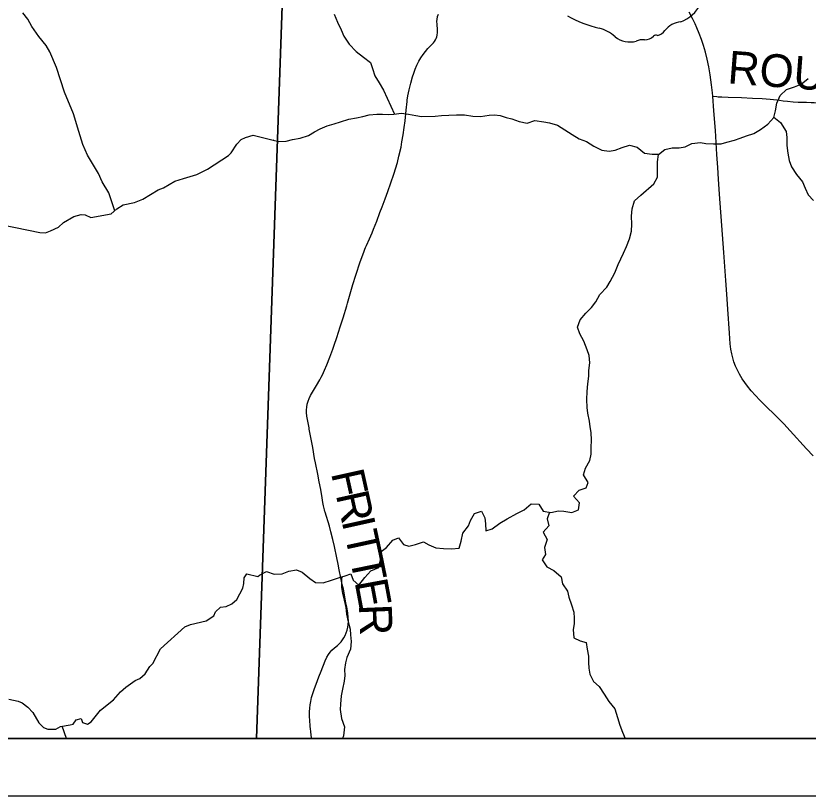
# Model space of a CAD drawing. Extents: x 0 to 34, y 0 to 22.
# Drawn here: x 28.101 to 29.474, y 14 to 15.353 of the extents above; entities that cross this region are included whole.
import ezdxf

# ---------------------------------------------------------------- set-up
doc = ezdxf.new("R2010")
doc.units = 0
for name, color, linetype in [('GM_X_Adjacent_County', 7, 'Continuous'), ('GM_X_County', 7, 'Continuous'), ('GM_X_County_Road', 7, 'Continuous'), ('GM_X_County_Road_Text', 7, 'Continuous'), ('GM_X_Minor_River', 7, 'Continuous'), ('GM_X_State_Route', 7, 'Continuous'), ('GM_X_State_Shield', 7, 'Continuous'), ('GM_X_Township', 7, 'Continuous'), ('SH_Data', 7, 'Continuous')]:
    doc.layers.add(name, color=color, linetype=linetype)

msp = doc.modelspace()

# ---------------------------------------------------------------- linework, layer by layer
at = {"layer": 'GM_X_Adjacent_County'}
for points in [[(28.7526, 20.9), (24.0167, 20.9), (24.0167, 14.1), (28.5181, 14.1)], [(28.5181, 14.1), (30.8167, 14.1), (30.8167, 20.9), (28.7526, 20.9)], [(28.5873, 16.0794), (28.5181, 14.1)], [(28.5181, 14.1), (28.5873, 16.0794)]]:
    msp.add_lwpolyline(points, dxfattribs=at)
at = {"layer": 'GM_X_County'}
for points in [[(28.7526, 20.9), (24.0167, 20.9), (24.0167, 14.1), (28.5181, 14.1)], [(28.5181, 14.1), (30.8167, 14.1), (30.8167, 20.9), (28.7526, 20.9)], [(28.5181, 14.1), (28.5873, 16.0794)], [(28.5873, 16.0794), (28.5181, 14.1)]]:
    msp.add_lwpolyline(points, dxfattribs=at)
at = {"layer": 'GM_X_County_Road'}
for points in [[(28.6133, 14.1), (28.6125, 14.1072), (28.6122, 14.1102), (28.6118, 14.1133), (28.6115, 14.1158), (28.6109, 14.122), (28.61, 14.1312), (28.6097, 14.138), (28.6097, 14.146), (28.61, 14.1528), (28.6106, 14.1582), (28.6117, 14.1643), (28.6134, 14.1709), (28.616, 14.1797), (28.6185, 14.1867), (28.6214, 14.1942), (28.6261, 14.207), (28.63, 14.2169), (28.637, 14.2347), (28.6398, 14.2408), (28.6425, 14.2456), (28.6453, 14.2496), (28.6485, 14.2532), (28.6532, 14.2572), (28.6581, 14.261), (28.6618, 14.2644), (28.6647, 14.2677), (28.667, 14.2707), (28.6693, 14.2744), (28.6713, 14.2783), (28.6732, 14.283), (28.6748, 14.2877), (28.676, 14.2932), (28.6767, 14.2976), (28.677, 14.3032), (28.6767, 14.3095), (28.6758, 14.3175), (28.6742, 14.328), (28.6729, 14.3353), (28.6683, 14.3585), (28.6665, 14.367), (28.6638, 14.3785), (28.6611, 14.3925), (28.6591, 14.4023), (28.6569, 14.4132), (28.6528, 14.4325), (28.65, 14.4446), (28.6465, 14.4584), (28.6442, 14.468), (28.6422, 14.4752), (28.6393, 14.4847), (28.6368, 14.4923), (28.6365, 14.4935), (28.6356, 14.4965), (28.6339, 14.503), (28.6328, 14.5091), (28.6316, 14.5171), (28.6291, 14.5318), (28.6266, 14.5446), (28.6239, 14.558), (28.6201, 14.5775), (28.6186, 14.5854), (28.6153, 14.6043), (28.6109, 14.6275), (28.6093, 14.6361), (28.6089, 14.6385), (28.608, 14.644), (28.6053, 14.6586), (28.6046, 14.6652), (28.6046, 14.6695), (28.6049, 14.6744), (28.6058, 14.6797), (28.6071, 14.6844), (28.6091, 14.6895), (28.6115, 14.6945), (28.6147, 14.7005), (28.6218, 14.712), (28.6275, 14.7216), (28.6299, 14.726), (28.6322, 14.7304), (28.6358, 14.7384), (28.6396, 14.7476), (28.6448, 14.7609), (28.65, 14.7749), (28.6525, 14.7819), (28.6569, 14.7949), (28.6629, 14.8132), (28.6681, 14.8291), (28.6742, 14.85), (28.6756, 14.8547), (28.6813, 14.875), (28.6849, 14.8869), (28.6899, 14.9029), (28.6974, 14.9259), (28.7018, 14.9382), (28.7042, 14.9445), (28.7056, 14.948), (28.7068, 14.9508), (28.7083, 14.9542), (28.7136, 14.966), (28.7181, 14.9762), (28.7207, 14.9825), (28.7261, 14.9964), (28.7317, 15.0114), (28.7354, 15.0212), (28.7409, 15.0356), (28.7453, 15.0479), (28.7505, 15.0631), (28.7559, 15.0783), (28.7619, 15.0982), (28.7647, 15.1091), (28.7682, 15.1248), (28.7699, 15.1339), (28.7719, 15.1461), (28.7738, 15.159), (28.7752, 15.1707), (28.7771, 15.1893), (28.7788, 15.2041), (28.779, 15.2065), (28.7801, 15.2138), (28.7823, 15.2241), (28.7851, 15.2356), (28.7882, 15.2469), (28.7902, 15.2534), (28.7928, 15.2603), (28.7957, 15.2671), (28.799, 15.2737), (28.8024, 15.2795), (28.8064, 15.2856), (28.8105, 15.2909), (28.8149, 15.296), (28.8191, 15.3004), (28.8243, 15.3058), (28.8263, 15.3082), (28.8281, 15.3108), (28.8293, 15.3131), (28.8303, 15.3161), (28.8309, 15.3193), (28.8314, 15.3237), (28.8314, 15.3287), (28.8306, 15.3374), (28.8304, 15.3435), (28.8306, 15.3464), (28.8316, 15.3512), (28.833, 15.3552)], [(29.3084, 15.2131), (29.3157, 15.2126), (29.3176, 15.2124), (29.3238, 15.2121), (29.335, 15.2116), (29.358, 15.2108), (29.3772, 15.21), (29.394, 15.2092), (29.4076, 15.2081), (29.4192, 15.2068), (29.4241, 15.2062), (29.4303, 15.2053), (29.4376, 15.2044), (29.4475, 15.2035), (29.4561, 15.2031), (29.4648, 15.2029), (29.471, 15.2027), (29.4791, 15.2024), (29.4841, 15.2021), (29.4909, 15.2011), (29.4982, 15.1998), (29.5059, 15.1981), (29.5129, 15.1967), (29.5262, 15.1936)]]:
    msp.add_lwpolyline(points, dxfattribs=at)
at = {"layer": 'GM_X_Minor_River'}
for points in [[(28.2722, 15.0146), (28.2618, 15.0455), (28.2503, 15.0648), (28.2441, 15.0791), (28.2249, 15.1113), (28.2168, 15.1294), (28.2098, 15.1518), (28.2009, 15.1829), (28.1854, 15.22), (28.1711, 15.2628), (28.1595, 15.2904), (28.1533, 15.301), (28.1407, 15.3168), (28.1285, 15.3338), (28.1219, 15.3467), (28.1131, 15.358)], [(28.6525, 15.3557), (28.6583, 15.3413), (28.6648, 15.328), (28.669, 15.3174), (28.6782, 15.3035), (28.6908, 15.2906), (28.7034, 15.2808), (28.7152, 15.2714), (28.7191, 15.2612), (28.723, 15.2487), (28.7306, 15.2362), (28.7379, 15.2234), (28.7445, 15.2101), (28.757, 15.1822)], [(29.1726, 15.0316), (29.1835, 15.0415), (29.2061, 15.0614), (29.2125, 15.0728), (29.2124, 15.0869), (29.2127, 15.0994), (29.2141, 15.112), (29.2254, 15.1211), (29.2379, 15.1235), (29.25, 15.124), (29.2603, 15.1252), (29.272, 15.1313), (29.2871, 15.1329), (29.2966, 15.1315), (29.3099, 15.1304), (29.3228, 15.1305), (29.3326, 15.1333), (29.3459, 15.1371), (29.3561, 15.1406), (29.3667, 15.1445), (29.3795, 15.1488), (29.3912, 15.1553), (29.4037, 15.1649), (29.4142, 15.1763), (29.4168, 15.1877), (29.4194, 15.2014), (29.425, 15.2144), (29.4363, 15.2251), (29.4499, 15.2293), (29.4616, 15.2343), (29.4737, 15.2439)], [(28.5473, 15.137), (28.5467, 15.1371), (28.5565, 15.1348), (28.5694, 15.1353), (28.5804, 15.138), (28.5933, 15.1404), (28.6077, 15.1451), (28.6182, 15.1512), (28.6284, 15.1566), (28.6405, 15.1616), (28.6523, 15.1651), (28.6636, 15.169), (28.6776, 15.1736), (28.6912, 15.176), (28.7018, 15.178), (28.7128, 15.1807), (28.7264, 15.1823), (28.7363, 15.182), (28.7465, 15.1813), (28.756, 15.1821), (28.7693, 15.1837), (28.781, 15.1823), (28.7939, 15.1797), (28.8038, 15.1783), (28.8273, 15.1784), (28.8383, 15.1796), (28.8512, 15.1805), (28.8641, 15.181), (28.8781, 15.1811), (28.8929, 15.1789), (28.9062, 15.1778), (28.921, 15.1802), (28.9304, 15.181), (28.9403, 15.1796), (28.9506, 15.1762), (28.9604, 15.174), (28.973, 15.1692), (28.9866, 15.1662), (29.0003, 15.1712), (29.0158, 15.1687), (29.0257, 15.1669), (29.0394, 15.1628), (29.0523, 15.1549), (29.0649, 15.147), (29.0767, 15.1395), (29.0896, 15.1346), (29.1022, 15.1268), (29.1162, 15.1196), (29.1291, 15.1182), (29.139, 15.1194), (29.1515, 15.1241), (29.1643, 15.1283), (29.1776, 15.1246), (29.1902, 15.1145), (29.2035, 15.1126), (29.2154, 15.113)], [(29.4143, 15.1767), (29.4257, 15.1677), (29.4353, 15.1518), (29.4365, 15.1416), (29.4369, 15.1275), (29.4385, 15.1146), (29.4405, 15.1017), (29.4448, 15.0907), (29.4532, 15.0775), (29.4639, 15.0647), (29.4682, 15.0537), (29.4735, 15.042), (29.4827, 15.0322)], [(28.078, 14.9903), (28.1426, 14.9771), (28.1524, 14.9764), (28.1607, 14.9798), (28.1747, 14.9864), (28.1834, 14.9941), (28.2015, 15.0048), (28.2143, 15.0083), (28.2212, 15.0076), (28.2307, 15.0031), (28.2662, 15.0091), (28.2756, 15.0179), (28.287, 15.0252), (28.3062, 15.0291), (28.321, 15.0345), (28.3474, 15.051), (28.3568, 15.0545), (28.3764, 15.066), (28.3912, 15.0707), (28.4146, 15.0773), (28.4331, 15.087), (28.4693, 15.1104), (28.4742, 15.115), (28.4839, 15.1302), (28.4911, 15.1379), (28.499, 15.1417), (28.5122, 15.1456), (28.5467, 15.1371)], [(28.5204, 14.3808), (28.5231, 14.3829), (28.5351, 14.3895), (28.5484, 14.3846), (28.5621, 14.3855), (28.5738, 14.3897), (28.5874, 14.3921), (28.5969, 14.3883), (28.6103, 14.377), (28.6198, 14.3703), (28.6331, 14.3696), (28.6478, 14.3746), (28.6615, 14.3789), (28.6713, 14.3816), (28.6811, 14.3851), (28.6854, 14.3741), (28.6953, 14.3655), (28.7054, 14.3788), (28.716, 14.3907), (28.7296, 14.3965), (28.7325, 14.4094), (28.7313, 14.4223), (28.743, 14.4311), (28.7539, 14.4437), (28.7641, 14.4476), (28.7725, 14.4362), (28.782, 14.4333), (28.7934, 14.436), (28.807, 14.4406), (28.8165, 14.4354), (28.8287, 14.4302), (28.8416, 14.4291), (28.8556, 14.4288), (28.8689, 14.4301), (28.8722, 14.4422), (28.8755, 14.4559), (28.8849, 14.4685), (28.8886, 14.478), (28.8958, 14.4898), (28.9079, 14.4941), (28.9132, 14.4824), (28.9145, 14.4721), (28.9149, 14.46), (28.9259, 14.4635), (28.9395, 14.4734), (28.9523, 14.4807), (28.9689, 14.49), (28.9818, 14.4961), (28.9938, 14.5068), (29.0071, 14.5062), (29.0148, 14.4937), (29.0277, 14.4919), (29.0409, 14.4946), (29.0504, 14.4939), (29.0641, 14.4917), (29.0758, 14.4964), (29.0772, 14.5082), (29.0673, 14.5202), (29.0767, 14.5306), (29.0892, 14.5344), (29.0925, 14.5439), (29.0845, 14.5568), (29.0878, 14.5686), (29.0953, 14.5816), (29.0975, 14.593), (29.0974, 14.6043), (29.0981, 14.6169), (29.0976, 14.6305), (29.096, 14.6404), (29.0948, 14.6499), (29.0921, 14.6639), (29.0905, 14.6738), (29.09, 14.6874), (29.0907, 14.7015), (29.0917, 14.7144), (29.0935, 14.7281), (29.0938, 14.7376), (29.0953, 14.7509), (29.094, 14.7638), (29.0909, 14.7736), (29.0848, 14.7884), (29.0779, 14.8013), (29.074, 14.813), (29.0788, 14.8256), (29.0886, 14.8374), (29.098, 14.8469), (29.1055, 14.8569), (29.1127, 14.8694), (29.1247, 14.8824), (29.1307, 14.8923), (29.1389, 14.9072), (29.1445, 14.9213), (29.149, 14.9312), (29.1539, 14.9411), (29.1587, 14.9529), (29.1643, 14.9662), (29.1676, 14.9792), (29.1679, 14.9917), (29.1678, 15.0053), (29.1685, 15.0179), (29.1726, 15.0316)], [(29.0255, 14.4922), (29.0213, 14.4808), (29.0241, 14.4687), (29.0147, 14.4576), (29.0212, 14.4447), (29.0171, 14.4311), (29.0187, 14.4189), (29.0127, 14.4094), (29.0208, 14.3973), (29.0329, 14.3913), (29.0459, 14.38), (29.0479, 14.3678), (29.0567, 14.3554), (29.059, 14.3451), (29.0637, 14.3319), (29.0676, 14.319), (29.068, 14.3088), (29.0681, 14.2985), (29.0663, 14.289), (29.0675, 14.2746), (29.0789, 14.269), (29.0892, 14.2664), (29.0908, 14.2546), (29.0931, 14.2425), (29.0932, 14.2318), (29.0936, 14.2216), (29.0952, 14.2113), (29.1018, 14.1985), (29.1113, 14.1902), (29.1205, 14.177), (29.1282, 14.1641), (29.1385, 14.1516), (29.1431, 14.1365), (29.1474, 14.1228), (29.1517, 14.1107), (29.1565, 14.1)], [(28.0886, 14.1683), (28.1049, 14.1646), (28.1118, 14.1616), (28.1217, 14.1545), (28.1305, 14.145), (28.1408, 14.1272), (28.1485, 14.1189), (28.1565, 14.1163), (28.1701, 14.1161), (28.1784, 14.1207), (28.1951, 14.1235), (28.2, 14.125), (28.2052, 14.1323), (28.2139, 14.1346), (28.2166, 14.1278), (28.225, 14.1248), (28.2314, 14.1287), (28.2475, 14.1489), (28.2701, 14.1669), (28.2821, 14.181), (28.2915, 14.1891), (28.3078, 14.2002), (28.3157, 14.2037), (28.3251, 14.2121), (28.3329, 14.2247), (28.3382, 14.2297), (28.3513, 14.2552), (28.3938, 14.2935), (28.4036, 14.2977), (28.4305, 14.304), (28.4437, 14.3125), (28.447, 14.3197), (28.4553, 14.3273), (28.4651, 14.3289), (28.4753, 14.3336), (28.484, 14.3408), (28.4941, 14.3607), (28.4959, 14.3687), (28.4966, 14.3782), (28.5011, 14.3854), (28.5204, 14.3808)], [(28.6664, 14.3803), (28.6653, 14.3774), (28.665, 14.3615), (28.6666, 14.352), (28.6697, 14.3395), (28.6724, 14.327), (28.6737, 14.3156), (28.6768, 14.3019), (28.6799, 14.2894), (28.6807, 14.2796), (28.682, 14.2678), (28.6809, 14.2545), (28.6742, 14.2404), (28.672, 14.2309), (28.6705, 14.2195), (28.671, 14.2092), (28.6695, 14.1994), (28.6666, 14.1853), (28.6648, 14.1739), (28.6634, 14.1594), (28.6627, 14.15), (28.6651, 14.1348), (28.6701, 14.1204), (28.6683, 14.1048), (28.6666, 14.1)], [(28.1885, 14.1), (28.181, 14.1211)]]:
    msp.add_lwpolyline(points, dxfattribs=at)
at = {"layer": 'GM_X_State_Route'}
msp.add_lwpolyline([(29.4825, 14.5897), (29.471, 14.6019), (29.4427, 14.6331), (29.4313, 14.6452), (29.4174, 14.6593), (29.3994, 14.6771), (29.3902, 14.6863), (29.3825, 14.6945), (29.375, 14.7028), (29.3686, 14.7105), (29.3637, 14.7169), (29.3591, 14.7236), (29.3547, 14.7312), (29.351, 14.7385), (29.348, 14.7453), (29.3451, 14.7529), (29.343, 14.7595), (29.3413, 14.7668), (29.3399, 14.7748), (29.3388, 14.7841), (29.3373, 14.8026), (29.3345, 14.8441), (29.3328, 14.8701), (29.3309, 14.8936), (29.3274, 14.9424), (29.3251, 14.9733), (29.3203, 15.0437), (29.3184, 15.0697), (29.317, 15.0895), (29.3156, 15.1124), (29.3129, 15.1539), (29.3103, 15.188), (29.3084, 15.2131), (29.3079, 15.219), (29.3064, 15.2331), (29.304, 15.2503), (29.3015, 15.2644), (29.2987, 15.2777), (29.2957, 15.2897), (29.2924, 15.301), (29.2889, 15.3116), (29.285, 15.322), (29.2809, 15.3317), (29.2778, 15.3385), (29.2732, 15.3479), (29.2673, 15.3588)], dxfattribs=at)
at = {"layer": 'GM_X_State_Shield'}
for centre, radius, start, end in [((29.2264, 15.4066), 0.0699, 292.3089, 8.9858), ((29.1563, 15.5281), 0.2019, 240.4129, 257.1985), ((29.2559, 15.3037), 0.0383, 94.4031, 142.5768), ((29.0961, 15.2699), 0.0632, 47.1842, 75.836), ((29.2073, 15.3405), 0.0226, 282.8732, 323.2771), ((29.1645, 15.3473), 0.0401, 230.7004, 286.2918), ((29.1876, 15.2781), 0.0329, 85.6951, 111.2099), ((29.1906, 15.3323), 0.0214, 268.777, 315.5493), ((29.2099, 15.3129), 0.00601, 65.7517, 132.6484)]:
    msp.add_arc(centre, radius, start, end, dxfattribs=at)
at = {"layer": 'GM_X_Township'}
for points in [[(24.0167, 18.4402), (24.0167, 14.1), (28.5181, 14.1)], [(28.5181, 14.1), (30.8167, 14.1), (30.8167, 18.1651)], [(28.5181, 14.1), (28.5873, 16.0794)], [(28.5873, 16.0794), (28.5181, 14.1)]]:
    msp.add_lwpolyline(points, dxfattribs=at)
at = {"layer": 'SH_Data'}
for points in [[(23.9167, 21), (30.9167, 21), (30.9167, 14), (23.9167, 14)], [(24.0167, 20.9), (30.8167, 20.9), (30.8167, 14.1), (24.0167, 14.1)]]:
    msp.add_lwpolyline(points, close=True, dxfattribs=at)

# ---------------------------------------------------------------- texts
at = {"layer": 'GM_X_County_Road_Text'}
for s, height, rotation, p in [('ROUGH', 0.05682, 355.5568, (29.3329, 15.2357)), ('F', 0.0568, 282.5293, (28.6467, 14.5601)), ('R', 0.0568, 282.5354, (28.655, 14.5227)), ('I', 0.0568, 282.5102, (28.6651, 14.4772)), ('T', 0.0568, 282.2601, (28.6702, 14.4544)), ('T', 0.0568, 281.5768, (28.6792, 14.4131)), ('E', 0.0568, 280.5463, (28.6876, 14.3717)), ('R', 0.0568, 272.3776, (28.6952, 14.3321))]:
    msp.add_text(s, height=height, rotation=rotation, dxfattribs=at).set_placement(p)

doc.saveas('drawing.dxf')
